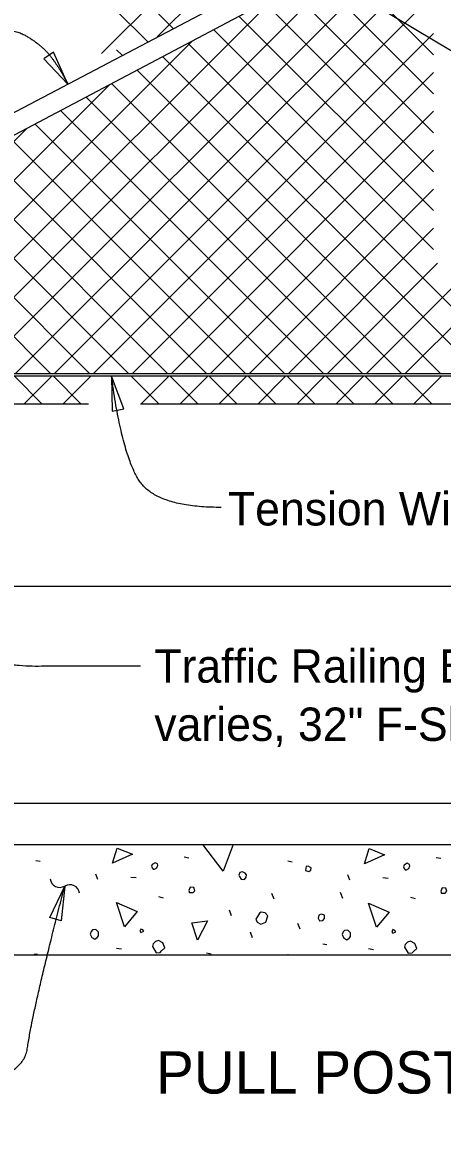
# Model space of a CAD drawing. Extents: x 110698 to 110915, y 110390 to 110472.
# Drawn here: x 110877.57 to 110880.11, y 110456.42 to 110463.25 of the extents above; entities that cross this region are included whole.
import ezdxf

# ---------------------------------------------------------------- set-up
doc = ezdxf.new("R2010")
doc.units = 0
for name, color, linetype in [('Border', 7, 'Continuous'), ('PlotBorder_dp', 7, 'Continuous'), ('SheetBorder_dp', 7, 'Continuous'), ('SheetLines_dp', 7, 'Continuous'), ('SupstrConc_h', 7, 'Continuous'), ('TextMisc', 7, 'Continuous')]:
    doc.layers.add(name, color=color, linetype=linetype)

msp = doc.modelspace()

# ---------------------------------------------------------------- linework, layer by layer
at = {"layer": 'PlotBorder_dp'}
for points in [[(110877.8469, 110462.8785), (110877.7599, 110463.071), (110877.7014, 110463.0316)], [(110878.111, 110461.1121), (110878.116, 110460.9009), (110878.1852, 110460.9143)], [(110877.8283, 110458.0281), (110877.806, 110457.8181), (110877.7381, 110457.8371)]]:
    msp.add_lwpolyline(points, close=True, dxfattribs=at)
for centre, start, end in [((110877.7991, 110458.0794), 188.42943, 300.15665), ((110877.859, 110457.9763), 8.42943, 120.15665)]:
    msp.add_arc(centre, 0.0596, start, end, dxfattribs=at)
for points in [[(110877.2631, 110463.2189), (110877.4945, 110463.2263), (110877.685, 110463.1191), (110877.7981, 110462.9761), (110877.8469, 110462.8785)], [(110878.774, 110460.3181), (110878.3761, 110460.3181), (110878.1721, 110460.6551), (110878.1109, 110461.112)], [(110878.2865, 110459.3569), (110877.9935, 110459.3569), (110877.294, 110459.3569), (110876.7363, 110459.6138)], [(110876.8897, 110456.8315), (110877.5655, 110456.792), (110877.6393, 110457.2993), (110877.8284, 110458.0281)]]:
    msp.add_open_spline(points, degree=2, dxfattribs=at)
at = {"layer": 'SheetBorder_dp'}
for p, q in [((110880.1074, 110465.1197), (110878.0507, 110463.063)), ((110880.3431, 110465.1197), (110878.3877, 110463.1643)), ((110881.0992, 110464.4616), (110877.7644, 110461.1268)), ((110880.5994, 110464.1975), (110877.5287, 110461.1268)), ((110880.0995, 110463.9333), (110877.293, 110461.1268)), ((110879.5997, 110463.6692), (110877.0573, 110461.1268)), ((110880.0585, 110463.0557), (110879.4985, 110463.6157)), ((110878.4845, 110463.2154), (110878.1419, 110463.558)), ((110880.0585, 110462.82), (110879.3442, 110463.5342)), ((110880.0585, 110462.5843), (110879.19, 110463.4527)), ((110879.0999, 110463.4051), (110876.8216, 110461.1268)), ((110880.0585, 110462.3486), (110879.0358, 110463.3712)), ((110878.3303, 110463.134), (110878.1419, 110463.3223)), ((110880.0585, 110462.1129), (110878.8816, 110463.2897)), ((110880.0585, 110463.1852), (110878.0001, 110461.1268)), ((110880.0585, 110461.8771), (110878.7274, 110463.2082)), ((110878.6, 110463.1409), (110876.5859, 110461.1268)), ((110878.1761, 110463.0525), (110878.1419, 110463.0866)), ((110880.5731, 110461.1268), (110878.5732, 110463.1267)), ((110880.3374, 110461.1268), (110878.419, 110463.0452)), ((110880.0585, 110462.9495), (110878.2358, 110461.1268)), ((110880.1017, 110461.1268), (110878.2648, 110462.9638)), ((110878.1002, 110462.8768), (110876.3502, 110461.1268)), ((110879.866, 110461.1268), (110878.1106, 110462.8823)), ((110879.6303, 110461.1268), (110877.9564, 110462.8008)), ((110879.3946, 110461.1268), (110877.8021, 110462.7193)), ((110880.0585, 110462.7138), (110878.4715, 110461.1268)), ((110877.6004, 110462.6127), (110876.1145, 110461.1268)), ((110879.1589, 110461.1268), (110877.6479, 110462.6378)), ((110878.9232, 110461.1268), (110877.4937, 110462.5563)), ((110878.6875, 110461.1268), (110877.3395, 110462.4748)), ((110880.0585, 110462.4781), (110878.7072, 110461.1268)), ((110878.4518, 110461.1268), (110877.1853, 110462.3933)), ((110878.2161, 110461.1268), (110877.0311, 110462.3118)), ((110877.9804, 110461.1268), (110876.8769, 110462.2303)), ((110880.0585, 110462.2424), (110878.9429, 110461.1268)), ((110877.7447, 110461.1268), (110876.7227, 110462.1488)), ((110880.0585, 110462.0067), (110879.1786, 110461.1268)), ((110880.083, 110461.7955), (110879.4143, 110461.1268)), ((110880.3187, 110461.7955), (110879.65, 110461.1268)), ((110880.5544, 110461.7955), (110879.8857, 110461.1268)), ((110877.6904, 110460.9454), (110877.5238, 110461.112)), ((110877.7497, 110461.112), (110877.583, 110460.9454)), ((110877.9261, 110460.9454), (110877.7595, 110461.112)), ((110877.9854, 110461.112), (110877.8187, 110460.9454)), ((110878.3975, 110460.9454), (110878.2309, 110461.112)), ((110878.4568, 110461.112), (110878.2901, 110460.9454)), ((110878.6332, 110460.9454), (110878.4666, 110461.112)), ((110878.6925, 110461.112), (110878.5258, 110460.9454)), ((110878.8689, 110460.9454), (110878.7023, 110461.112)), ((110878.9282, 110461.112), (110878.7615, 110460.9454)), ((110879.1046, 110460.9454), (110878.938, 110461.112)), ((110879.1639, 110461.112), (110878.9972, 110460.9454)), ((110879.3404, 110460.9454), (110879.1737, 110461.112)), ((110879.3996, 110461.112), (110879.2329, 110460.9454)), ((110879.5761, 110460.9454), (110879.4094, 110461.112)), ((110879.6353, 110461.112), (110879.4686, 110460.9454)), ((110879.8118, 110460.9454), (110879.6451, 110461.112)), ((110879.871, 110461.112), (110879.7043, 110460.9454)), ((110880.0475, 110460.9454), (110879.8808, 110461.112)), ((110880.1067, 110461.112), (110879.94, 110460.9454)), ((110877.6532, 110458.1832), (110877.6798, 110458.1779)), ((110878.5513, 110458.2045), (110878.5778, 110458.1992)), ((110879.1771, 110458.1797), (110879.2036, 110458.1744)), ((110880.0751, 110458.2009), (110880.1016, 110458.1956)), ((110878.028, 110458.0666), (110878.0156, 110458.1002)), ((110878.2278, 110458.0825), (110878.2596, 110458.0789)), ((110879.5518, 110458.063), (110879.5394, 110458.0966)), ((110879.7516, 110458.0789), (110879.7834, 110458.0754)), ((110878.3957, 110457.964), (110878.424, 110457.957)), ((110879.094, 110457.9481), (110879.0798, 110457.9835)), ((110879.5094, 110457.9534), (110879.4953, 110457.9888)), ((110879.9195, 110457.9605), (110879.9478, 110457.9534)), ((110878.8376, 110457.8474), (110878.8235, 110457.8827)), ((110879.2513, 110457.7661), (110879.2372, 110457.8014)), ((110878.9632, 110457.7148), (110878.9508, 110457.7484)), ((110878.1411, 110457.6529), (110878.1712, 110457.6476)), ((110878.6856, 110457.6246), (110878.7139, 110457.6176)), ((110879.3892, 110457.6777), (110879.4139, 110457.6741)), ((110879.665, 110457.6494), (110879.695, 110457.6441))]:
    msp.add_line(p, q, dxfattribs=at)
for points in [[(110878.1164, 110458.1656), (110878.1447, 110458.2575), (110878.2384, 110458.2204), (110878.1164, 110458.1656)], [(110878.7864, 110458.1178), (110878.6641, 110458.2787)], [(110878.8465, 110458.2787), (110878.7864, 110458.1178)], [(110879.6402, 110458.162), (110879.6685, 110458.254), (110879.7622, 110458.2168), (110879.6402, 110458.162)], [(110878.3639, 110458.1302), (110878.371, 110458.1302), (110878.3851, 110458.1373), (110878.3904, 110458.1532), (110878.3886, 110458.162), (110878.3745, 110458.1691), (110878.3568, 110458.1585), (110878.3533, 110458.1479), (110878.3568, 110458.1373), (110878.3639, 110458.1302)], [(110879.8877, 110458.1267), (110879.8948, 110458.1267), (110879.9089, 110458.1337), (110879.9142, 110458.1497), (110879.9124, 110458.1585), (110879.8983, 110458.1656), (110879.8806, 110458.155), (110879.8771, 110458.1444), (110879.8806, 110458.1337), (110879.8877, 110458.1267)], [(110878.8854, 110458.086), (110878.8942, 110458.0701), (110878.9154, 110458.0666), (110878.9243, 110458.0825), (110878.9278, 110458.0966), (110878.919, 110458.1055), (110878.9031, 110458.1143), (110878.8871, 110458.109), (110878.8818, 110458.0931), (110878.8854, 110458.086)], [(110879.2849, 110458.1214), (110879.3043, 110458.1161), (110879.3167, 110458.1249), (110879.3185, 110458.1373), (110879.3149, 110458.1408), (110879.3008, 110458.1479), (110879.2884, 110458.1461), (110879.2867, 110458.1337), (110879.2849, 110458.1214)], [(110878.5831, 110457.9888), (110878.6043, 110457.9888), (110878.6149, 110457.9994), (110878.6096, 110458.0188), (110878.5866, 110458.0206), (110878.5831, 110458.01), (110878.5778, 110458.0012), (110878.5831, 110457.9888), (110878.5796, 110457.9923)], [(110880.1069, 110457.9853), (110880.1281, 110457.9853), (110880.1387, 110457.9959), (110880.1334, 110458.0153), (110880.1104, 110458.0171), (110880.1069, 110458.0065), (110880.1016, 110457.9976), (110880.1069, 110457.9853), (110880.1034, 110457.9888)], [(110878.1889, 110457.782), (110878.1411, 110457.9287), (110878.2667, 110457.8739), (110878.1889, 110457.782)], [(110879.7127, 110457.7784), (110879.665, 110457.9252), (110879.7905, 110457.8704), (110879.7127, 110457.7784)], [(110878.9914, 110457.8102), (110879.0144, 110457.7979), (110879.0445, 110457.8102), (110879.0568, 110457.8474), (110879.0392, 110457.865), (110879.0162, 110457.8704), (110879.0056, 110457.8633), (110878.9932, 110457.8438), (110878.9844, 110457.8279), (110878.9914, 110457.8102)], [(110879.3609, 110457.8332), (110879.3697, 110457.8173), (110879.3892, 110457.8191), (110879.398, 110457.8315), (110879.3998, 110457.8509), (110879.3874, 110457.8562), (110879.3786, 110457.858), (110879.368, 110457.8544), (110879.3644, 110457.8509), (110879.3609, 110457.8332)], [(110877.982, 110457.7378), (110877.9927, 110457.7166), (110878.0103, 110457.7059), (110878.0245, 110457.7166), (110878.0315, 110457.7272), (110878.0315, 110457.7484), (110878.0156, 110457.7643), (110877.9962, 110457.7625), (110877.9873, 110457.7537), (110877.982, 110457.7378)], [(110878.2879, 110457.7466), (110878.3073, 110457.7554), (110878.3002, 110457.7625), (110878.2879, 110457.7678), (110878.2826, 110457.7554), (110878.2879, 110457.7466)], [(110878.6308, 110457.7006), (110878.5972, 110457.8049), (110878.6909, 110457.8173), (110878.6308, 110457.7006)], [(110879.5059, 110457.7342), (110879.5165, 110457.713), (110879.5341, 110457.7024), (110879.5483, 110457.713), (110879.5554, 110457.7236), (110879.5554, 110457.7448), (110879.5394, 110457.7607), (110879.52, 110457.759), (110879.5112, 110457.7501), (110879.5059, 110457.7342)], [(110879.8117, 110457.7431), (110879.8311, 110457.7519), (110879.8241, 110457.759), (110879.8117, 110457.7643), (110879.8064, 110457.7519), (110879.8117, 110457.7431)], [(110878.3586, 110457.6618), (110878.3816, 110457.6246), (110878.4045, 110457.6264), (110878.4134, 110457.6352), (110878.4328, 110457.6547), (110878.4205, 110457.6847), (110878.3957, 110457.6989), (110878.378, 110457.6918), (110878.3639, 110457.6777), (110878.3586, 110457.6618)], [(110879.8824, 110457.6582), (110879.9054, 110457.6211), (110879.9284, 110457.6229), (110879.9372, 110457.6317), (110879.9566, 110457.6511), (110879.9443, 110457.6812), (110879.9195, 110457.6953), (110879.9018, 110457.6883), (110879.8877, 110457.6741), (110879.8824, 110457.6582)], [(110877.6642, 110457.612), (110877.6638, 110457.614), (110877.655, 110457.6158), (110877.6426, 110457.614), (110877.6406, 110457.612)], [(110879.1799, 110457.612), (110879.1788, 110457.6123), (110879.1773, 110457.612)]]:
    msp.add_lwpolyline(points, dxfattribs=at)
at = {"layer": 'SheetLines_dp'}
for p, q in [((110866.0939, 110471.5234), (110914.9915, 110442.1849)), ((110873.4424, 110460.9454), (110877.9727, 110460.9454)), ((110878.2859, 110460.9454), (110884.6836, 110460.9454)), ((110873.4424, 110459.8412), (110884.6836, 110459.8412)), ((110873.4424, 110458.2787), (110896.2163, 110458.2787)), ((110873.4424, 110457.612), (110896.2163, 110457.612))]:
    msp.add_line(p, q, dxfattribs=at)
at = {"layer": 'SupstrConc_h'}
msp.add_line((110873.4424, 110458.5287), (110896.2163, 110458.5287), dxfattribs=at)
at = {"layer": 'TextMisc'}
for p, q in [((110875.1767, 110461.4674), (110884.4263, 110466.3554)), ((110875.2327, 110461.3615), (110884.4824, 110466.2494)), ((110884.5214, 110461.112), (110875.1237, 110461.112)), ((110884.5201, 110461.1268), (110875.1503, 110461.1268))]:
    msp.add_line(p, q, dxfattribs=at)

# ---------------------------------------------------------------- texts
at = {"layer": 'Border'}
for s, height, p in [('Tension Wire', 0.2016, (110878.8149, 110460.2088)), ('PULL POST ASSEMBLY DETAIL FOR TRAFFIC RAILING BARRIERS', 0.256001, (110878.3805, 110456.7727))]:
    msp.add_text(s, height=height, dxfattribs=at).set_placement(p)
at = {"layer": 'PlotBorder_dp'}
for s, p in [('Traffic Railing Barrier (Type ', (110878.3699, 110459.2579)), ('varies, 32" F-Shape shown)', (110878.3699, 110458.9059))]:
    msp.add_text(s, height=0.2016, dxfattribs=at).set_placement(p)

doc.saveas('drawing.dxf')
